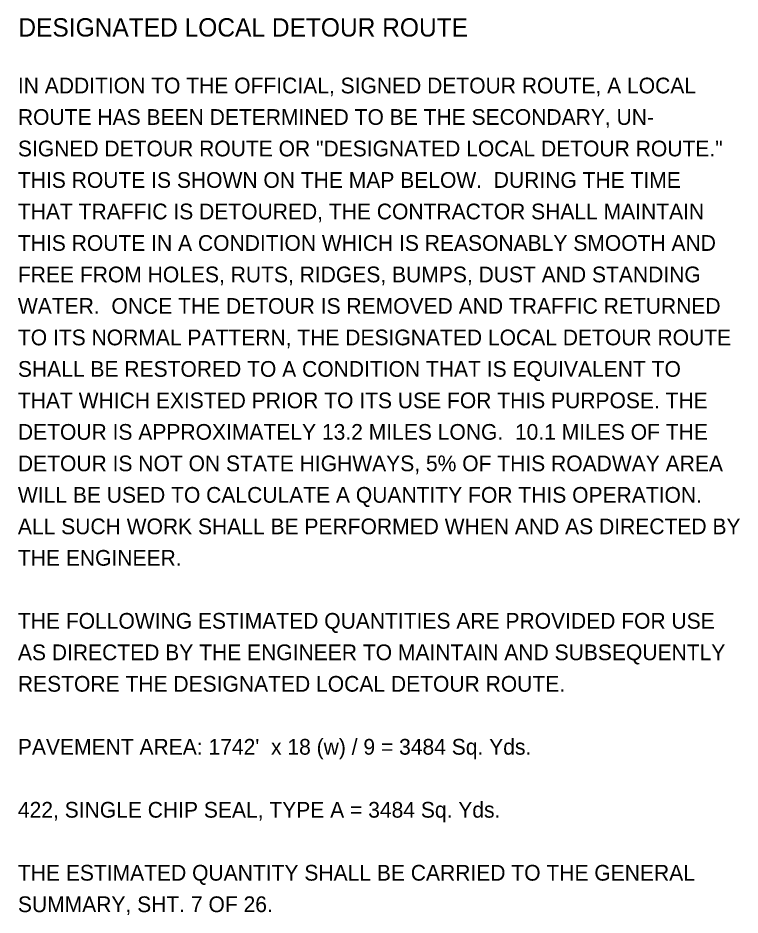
# Model space of a CAD drawing. Extents: x -452339 to 6403467, y -1 to 1814750.
# Drawn here: x -293888 to -256091, y 1627773 to 1674705 of the extents above; entities that cross this region are included whole.
import ezdxf

# ---------------------------------------------------------------- set-up
doc = ezdxf.new("R2010")
doc.units = 0
doc.layers.add('Default', color=7, linetype='Continuous')

msp = doc.modelspace()

# ---------------------------------------------------------------- texts
at = {"layer": 'Default'}
for s, height, p in [('DESIGNATED LOCAL DETOUR ROUTE', 959.9, (-293866, 1673730)), ('IN ADDITION TO THE OFFICIAL, SIGNED DETOUR ROUTE, A LOCAL', 823.68, (-293890, 1670757)), ('ROUTE HAS BEEN DETERMINED TO BE THE SECONDARY, UN-', 823.68, (-293890, 1669110)), ('SIGNED DETOUR ROUTE OR "DESIGNATED LOCAL DETOUR ROUTE."', 823.68, (-293890, 1667462)), ('THIS ROUTE IS SHOWN ON THE MAP BELOW.  DURING THE TIME', 823.68, (-293890, 1665815)), ('THAT TRAFFIC IS DETOURED, THE CONTRACTOR SHALL MAINTAIN', 823.68, (-293890, 1664168)), ('THIS ROUTE IN A CONDITION WHICH IS REASONABLY SMOOTH AND', 823.68, (-293890, 1662520)), ('FREE FROM HOLES, RUTS, RIDGES, BUMPS, DUST AND STANDING', 823.68, (-293890, 1660873)), ('WATER.  ONCE THE DETOUR IS REMOVED AND TRAFFIC RETURNED', 823.68, (-293890, 1659226)), ('TO ITS NORMAL PATTERN, THE DESIGNATED LOCAL DETOUR ROUTE', 823.68, (-293890, 1657578)), ('SHALL BE RESTORED TO A CONDITION THAT IS EQUIVALENT TO', 823.68, (-293890, 1655931)), ('THAT WHICH EXISTED PRIOR TO ITS USE FOR THIS PURPOSE. THE', 823.68, (-293890, 1654284)), ('DETOUR IS APPROXIMATELY 13.2 MILES LONG.  10.1 MILES OF THE', 823.68, (-293890, 1652636)), ('DETOUR IS NOT ON STATE HIGHWAYS, 5% OF THIS ROADWAY AREA', 823.68, (-293890, 1650989)), ('WILL BE USED TO CALCULATE A QUANTITY FOR THIS OPERATION.', 823.68, (-293890, 1649342)), ('ALL SUCH WORK SHALL BE PERFORMED WHEN AND AS DIRECTED BY', 823.68, (-293890, 1647694)), ('THE ENGINEER.', 823.68, (-293890, 1646047)), ('THE FOLLOWING ESTIMATED QUANTITIES ARE PROVIDED FOR USE', 823.68, (-293890, 1642752)), ('AS DIRECTED BY THE ENGINEER TO MAINTAIN AND SUBSEQUENTLY', 823.68, (-293890, 1641105)), ('RESTORE THE DESIGNATED LOCAL DETOUR ROUTE.', 823.68, (-293890, 1639457)), ("PAVEMENT AREA: 1742'  x 18 (w) / 9 = 3484 Sq. Yds.", 823.68, (-293890, 1636163)), ('422, SINGLE CHIP SEAL, TYPE A = 3484 Sq. Yds.', 823.68, (-293890, 1632868)), ('THE ESTIMATED QUANTITY SHALL BE CARRIED TO THE GENERAL', 823.68, (-293890, 1629573)), ('SUMMARY, SHT. 7 OF 26.', 823.68, (-293890, 1627926))]:
    msp.add_text(s, height=height, dxfattribs=at).set_placement(p)

doc.saveas('drawing.dxf')
